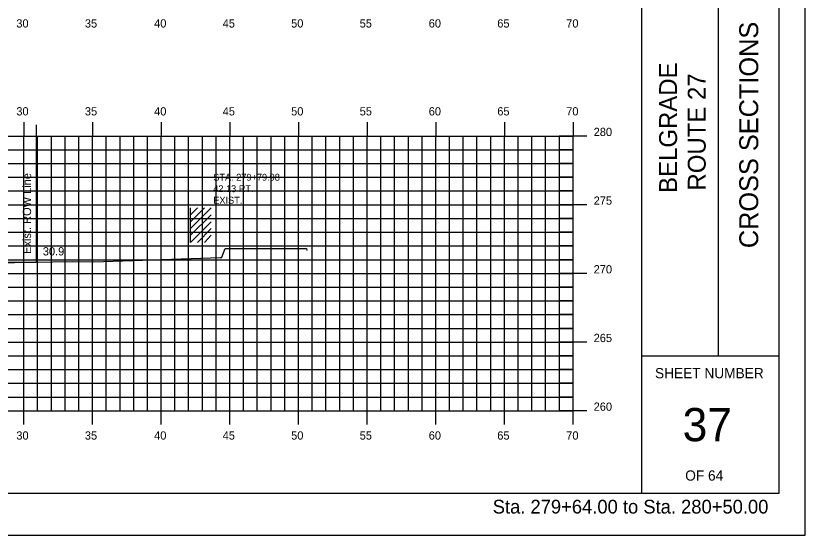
# Model space of a CAD drawing. Extents: x 855121 to 855291, y 366268 to 366378.
# Drawn here: x 855233.9 to 855291.3, y 366268.2 to 366306 of the extents above; entities that cross this region are included whole.
import ezdxf

# ---------------------------------------------------------------- set-up
doc = ezdxf.new("R2010")
doc.units = 0
for name, color, linetype in [('BORDER', 7, 'Continuous'), ('D_Roadway_FinishedGrade', 7, 'Continuous'), ('D_Text_Monospaced', 7, 'Continuous'), ('D_Text_Standard', 7, 'Continuous'), ('E_ROW_Line', 7, 'Continuous'), ('H_V ANNOTATION', 7, 'Continuous'), ('HIGHWAY_TITLE', 7, 'Continuous'), ('MAJOR', 7, 'Continuous'), ('MINOR', 7, 'Continuous'), ('PLOT BOUNDARY', 7, 'Continuous'), ('S_Buildings_SillElevation', 7, 'Continuous'), ('S_Roadway_Centerline', 7, 'Continuous')]:
    doc.layers.add(name, color=color, linetype=linetype)

msp = doc.modelspace()

# ---------------------------------------------------------------- linework, layer by layer
at = {"layer": 'BORDER'}
for p, q in [((855279.442, 366271.236), (855279.442, 366376.239)), ((855289.442, 366271.236), (855289.442, 366376.236)), ((855285.033, 366281.239), (855285.033, 366316.239)), ((855279.442, 366281.239), (855289.442, 366281.239)), ((855129.442, 366271.236), (855289.442, 366271.236))]:
    msp.add_line(p, q, dxfattribs=at)
at = {"layer": 'D_Roadway_FinishedGrade'}
msp.add_line((855228.448, 366288.056), (855235.338, 366288.056), dxfattribs=at)
at = {"layer": 'E_ROW_Line'}
msp.add_line((855235.365, 366288.056), (855235.365, 366298.056), dxfattribs=at)
at = {"layer": 'MAJOR'}
for p, q in [((855234.442, 366298.238), (855234.442, 366297.236)), ((855239.442, 366298.238), (855239.442, 366297.236)), ((855244.442, 366298.238), (855244.442, 366297.236)), ((855249.442, 366298.238), (855249.442, 366297.236)), ((855254.442, 366298.238), (855254.442, 366297.236)), ((855259.442, 366298.238), (855259.442, 366297.236)), ((855264.442, 366298.238), (855264.442, 366297.236)), ((855269.442, 366298.238), (855269.442, 366297.236)), ((855274.442, 366298.238), (855274.442, 366297.236)), ((855134.442, 366297.236), (855274.442, 366297.236)), ((855134.442, 366297.236), (855274.442, 366297.236)), ((855234.442, 366277.236), (855234.442, 366297.236)), ((855239.442, 366277.236), (855239.442, 366297.236)), ((855244.442, 366277.236), (855244.442, 366297.236)), ((855249.442, 366277.236), (855249.442, 366297.236)), ((855254.442, 366277.236), (855254.442, 366297.236)), ((855259.442, 366277.236), (855259.442, 366297.236)), ((855264.442, 366277.236), (855264.442, 366297.236)), ((855269.442, 366277.236), (855269.442, 366297.236)), ((855275.444, 366297.236), (855273.44, 366297.236)), ((855274.442, 366277.236), (855274.442, 366297.236)), ((855274.442, 366277.236), (855274.442, 366297.236)), ((855134.442, 366292.236), (855274.442, 366292.236)), ((855275.444, 366292.236), (855273.44, 366292.236)), ((855134.442, 366287.236), (855274.442, 366287.236)), ((855275.444, 366287.236), (855273.44, 366287.236)), ((855134.442, 366282.236), (855274.442, 366282.236)), ((855275.444, 366282.236), (855273.44, 366282.236)), ((855134.442, 366277.236), (855274.442, 366277.236)), ((855134.442, 366277.236), (855274.442, 366277.236)), ((855234.442, 366276.234), (855234.442, 366277.236)), ((855239.442, 366276.234), (855239.442, 366277.236)), ((855244.442, 366276.234), (855244.442, 366277.236)), ((855249.442, 366276.234), (855249.442, 366277.236)), ((855254.442, 366276.234), (855254.442, 366277.236)), ((855259.442, 366276.234), (855259.442, 366277.236)), ((855264.442, 366276.234), (855264.442, 366277.236)), ((855269.442, 366276.234), (855269.442, 366277.236)), ((855275.444, 366277.236), (855273.44, 366277.236)), ((855274.442, 366276.234), (855274.442, 366277.236))]:
    msp.add_line(p, q, dxfattribs=at)
at = {"layer": 'MINOR'}
for p, q in [((855235.442, 366277.236), (855235.442, 366297.236)), ((855236.442, 366277.236), (855236.442, 366297.236)), ((855237.442, 366277.236), (855237.442, 366297.236)), ((855238.442, 366277.236), (855238.442, 366297.236)), ((855240.442, 366277.236), (855240.442, 366297.236)), ((855241.442, 366277.236), (855241.442, 366297.236)), ((855242.442, 366277.236), (855242.442, 366297.236)), ((855243.442, 366277.236), (855243.442, 366297.236)), ((855245.442, 366277.236), (855245.442, 366297.236)), ((855246.442, 366277.236), (855246.442, 366297.236)), ((855247.442, 366277.236), (855247.442, 366297.236)), ((855248.442, 366277.236), (855248.442, 366297.236)), ((855250.442, 366277.236), (855250.442, 366297.236)), ((855251.442, 366277.236), (855251.442, 366297.236)), ((855252.442, 366277.236), (855252.442, 366297.236)), ((855253.442, 366277.236), (855253.442, 366297.236)), ((855255.442, 366277.236), (855255.442, 366297.236)), ((855256.442, 366277.236), (855256.442, 366297.236)), ((855257.442, 366277.236), (855257.442, 366297.236)), ((855258.442, 366277.236), (855258.442, 366297.236)), ((855260.442, 366277.236), (855260.442, 366297.236)), ((855261.442, 366277.236), (855261.442, 366297.236)), ((855262.442, 366277.236), (855262.442, 366297.236)), ((855263.442, 366277.236), (855263.442, 366297.236)), ((855265.442, 366277.236), (855265.442, 366297.236)), ((855266.442, 366277.236), (855266.442, 366297.236)), ((855267.442, 366277.236), (855267.442, 366297.236)), ((855268.442, 366277.236), (855268.442, 366297.236)), ((855270.442, 366277.236), (855270.442, 366297.236)), ((855271.442, 366277.236), (855271.442, 366297.236)), ((855272.442, 366277.236), (855272.442, 366297.236)), ((855273.442, 366277.236), (855273.442, 366297.236)), ((855134.442, 366296.236), (855274.442, 366296.236)), ((855274.442, 366296.236), (855273.44, 366296.236)), ((855134.442, 366295.236), (855274.442, 366295.236)), ((855274.442, 366295.236), (855273.44, 366295.236)), ((855134.442, 366294.236), (855274.442, 366294.236)), ((855274.442, 366294.236), (855273.44, 366294.236)), ((855134.442, 366293.236), (855274.442, 366293.236)), ((855274.442, 366293.236), (855273.44, 366293.236)), ((855134.442, 366291.236), (855274.442, 366291.236)), ((855274.442, 366291.236), (855273.44, 366291.236)), ((855134.442, 366290.236), (855274.442, 366290.236)), ((855274.442, 366290.236), (855273.44, 366290.236)), ((855134.442, 366289.236), (855274.442, 366289.236)), ((855274.442, 366289.236), (855273.44, 366289.236)), ((855134.442, 366288.236), (855274.442, 366288.236)), ((855274.442, 366288.236), (855273.44, 366288.236)), ((855134.442, 366286.236), (855274.442, 366286.236)), ((855274.442, 366286.236), (855273.44, 366286.236)), ((855134.442, 366285.236), (855274.442, 366285.236)), ((855274.442, 366285.236), (855273.44, 366285.236)), ((855134.442, 366284.236), (855274.442, 366284.236)), ((855274.442, 366284.236), (855273.44, 366284.236)), ((855134.442, 366283.236), (855274.442, 366283.236)), ((855274.442, 366283.236), (855273.44, 366283.236)), ((855134.442, 366281.236), (855274.442, 366281.236)), ((855274.442, 366281.236), (855273.44, 366281.236)), ((855134.442, 366280.236), (855274.442, 366280.236)), ((855274.442, 366280.236), (855273.44, 366280.236)), ((855134.442, 366279.236), (855274.442, 366279.236)), ((855274.442, 366279.236), (855273.44, 366279.236)), ((855134.442, 366278.236), (855274.442, 366278.236)), ((855274.442, 366278.236), (855273.44, 366278.236))]:
    msp.add_line(p, q, dxfattribs=at)
at = {"layer": 'PLOT BOUNDARY'}
msp.add_lwpolyline([(855121.349, 366268.177), (855291.349, 366268.177), (855291.349, 366378.177), (855121.349, 366378.177)], close=True, dxfattribs=at)
at = {"layer": 'S_Buildings_SillElevation'}
for p, q in [((855246.568, 366289.488), (855246.568, 366292.014)), ((855246.568, 366290.505), (855248.077, 366292.014)), ((855246.568, 366290.997), (855247.585, 366292.014)), ((855246.568, 366291.489), (855247.093, 366292.014)), ((855246.568, 366290.013), (855248.077, 366291.489)), ((855246.568, 366289.488), (855248.077, 366290.997)), ((855247.093, 366289.488), (855248.077, 366290.505)), ((855247.585, 366289.488), (855248.077, 366290.013))]:
    msp.add_line(p, q, dxfattribs=at)
at = {"layer": 'S_Roadway_Centerline'}
msp.add_lwpolyline([(855228.12, 366287.931), (855237.955, 366288.101), (855239.526, 366288.087), (855248.732, 366288.393), (855248.74, 366288.394), (855248.849, 366288.4), (855248.854, 366288.409), (855249.104, 366289.054), (855254.383, 366289.048), (855255.03, 366289.056), (855255.06, 366288.908)], dxfattribs=at)

# ---------------------------------------------------------------- texts
at = {"layer": 'BORDER'}
for s, height, rotation, p in [('CROSS SECTIONS', 1.37787, 90, (855287.927, 366289.073)), ('SHEET NUMBER', 0.74527, 360, (855280.408, 366279.603)), ('37', 2.4194, 360, (855282.418, 366275.019)), ('OF 64', 0.7453, 360, (855282.609, 366272.149))]:
    msp.add_text(s, height=height, rotation=rotation, dxfattribs=at).set_placement(p)
at = {"layer": 'D_Text_Monospaced'}
for s, height, p in [('STA. 279+79.98', 0.49998, (855248.234, 366293.986)), ('42.13 RT.', 0.5, (855248.234, 366293.152)), ('EXIST. ', 0.5, (855248.234, 366292.312))]:
    msp.add_text(s, height=height, dxfattribs=at).set_placement(p)
at = {"layer": 'D_Text_Standard'}
msp.add_text("30.9'", height=0.6, dxfattribs=at).set_placement((855235.82, 366288.544))
at = {"layer": 'E_ROW_Line'}
msp.add_text('Exist. ROW Line', height=0.6, rotation=90, dxfattribs=at).set_placement((855234.965, 366288.656))
at = {"layer": 'H_V ANNOTATION'}
for s, height, p in [('30', 0.6, (855233.891, 366305.136)), ('35', 0.6, (855238.883, 366305.136)), ('40', 0.6, (855243.928, 366305.136)), ('45', 0.6, (855248.92, 366305.136)), ('50', 0.6, (855253.907, 366305.136)), ('55', 0.6, (855258.899, 366305.136)), ('60', 0.6, (855263.928, 366305.136)), ('65', 0.6, (855268.92, 366305.136)), ('70', 0.6, (855273.944, 366305.136)), ('30', 0.6, (855233.891, 366298.736)), ('35', 0.6, (855238.883, 366298.736)), ('40', 0.6, (855243.928, 366298.736)), ('45', 0.6, (855248.92, 366298.736)), ('50', 0.6, (855253.907, 366298.736)), ('55', 0.6, (855258.899, 366298.736)), ('60', 0.6, (855263.928, 366298.736)), ('65', 0.6, (855268.92, 366298.736)), ('70', 0.6, (855273.944, 366298.736)), ('280', 0.6, (855275.942, 366297.236)), ('275', 0.6, (855275.942, 366292.236)), ('270', 0.6, (855275.942, 366287.236)), ('265', 0.6, (855275.942, 366282.236)), ('260', 0.6, (855275.942, 366277.236)), ('30', 0.6, (855233.891, 366275.136)), ('35', 0.6, (855238.883, 366275.136)), ('40', 0.6, (855243.928, 366275.136)), ('45', 0.6, (855248.92, 366275.136)), ('50', 0.6, (855253.907, 366275.136)), ('55', 0.6, (855258.899, 366275.136)), ('60', 0.6, (855263.928, 366275.136)), ('65', 0.6, (855268.92, 366275.136)), ('70', 0.6, (855273.944, 366275.136)), ('Sta. 279+64.00 to Sta. 280+50.00', 1.0002, (855268.588, 366269.756))]:
    msp.add_text(s, height=height, dxfattribs=at).set_placement(p)
at = {"layer": 'HIGHWAY_TITLE'}
for s, p in [('BELGRADE', (855282.014, 366293.095)), ('ROUTE 27', (855284.101, 366293.269))]:
    msp.add_text(s, height=1.3043, rotation=90, dxfattribs=at).set_placement(p)

doc.saveas('drawing.dxf')
